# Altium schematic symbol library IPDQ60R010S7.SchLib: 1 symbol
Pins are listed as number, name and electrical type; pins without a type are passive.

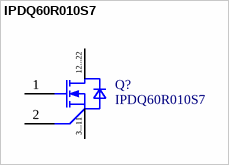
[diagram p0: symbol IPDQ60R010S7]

## IPDQ60R010S7
designator Q?
Insulated-Gate Field-Effect Transistor (IGFET), N-Channel, Enhancement, Body Diode, Pin 1 Gate, 2 Driver Source, 3 Power Source, 4 Power Source, 5 Power Source, 6 Power Source, 7 Power Source, 8 Power Source, 9 Power Source, 10 Power Source, 11 Power Source, 12 Drain, 13 Drain, 14 Drain, 15 Drain, 16 Drain, 17 Drain, 18 Drain, 19 Drain, 20 Drain, 21 Drain, 22 Drain, 22 Pins; Manufacturer: Infineon Technologies
pins: 1 GATE, 2 DRIVER SOURCE, 3 POWER SOURCE1, 4 POWER SOURCE2, 5 POWER SOURCE3, 6 POWER SOURCE4, 7 POWER SOURCE5, 8 POWER SOURCE6, 9 POWER SOURCE7, 10 POWER SOURCE8, 11 POWER SOURCE9, 12 DRAIN1, 13 DRAIN2, 14 DRAIN3, 15 DRAIN4, 16 DRAIN5, 17 DRAIN6, 18 DRAIN7, 19 DRAIN8, 20 DRAIN9, 21 DRAIN10, 22 DRAIN11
